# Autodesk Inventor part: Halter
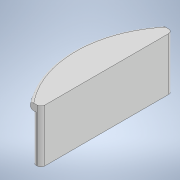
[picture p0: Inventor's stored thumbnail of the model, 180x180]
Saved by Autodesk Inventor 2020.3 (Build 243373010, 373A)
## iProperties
Created: 2020-07
Part Number: Halter
Material: Generisch
Document SubType Name: Modeling
Designer: Ruben
Density: 1 g/cm^3
Appearance: Vorgabe
Author: Ruben
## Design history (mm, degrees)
sketch "Skizze1"
  geometry: L1 (0, 0)-(0, 50); L2 (0, 0)-(45.605, 0); L3 (0, 50)-(5, 50); L4 (0, -50)-(5, -50); L5 (0, 50)-(0, -50); A1 r 80 centre (-57.45, 0) between (5, -50) and (5, 50)
  constraints: 10 end point, 2 horizontal, 2 point on circle, 2 symmetric about line, 1 centre point, 1 collinear, 1 vertical
  dimensions: "d0" = 50 distance of L1.start L1.end; "d1" = 5 distance of L1.end L3.end; "d2" = 80 radius of A1
extrude "Bogen" new body sketch "Skizze1" distance "d3" = 40; taper "d4" = 0 deg
sketch "Skizze2"
  geometry: L1 (-5, -50)-(-8, -50); L2 (0, 0)-(-34.59, 0); L3 (-5, 50)-(-8, 50); A1 r 80 centre (57.45, 0) between (-5, 50) and (-5, -50) reference; A2 r 80 centre (54.45, 0) between (-8, 50) and (-8, -50)
  constraints: 6 end point, 2 horizontal, 2 point on circle, 1 centre point, 1 equal radius, 1 symmetric about line
  dimensions: "d5" = 3 distance of L1.start L1.end
extrude "Lippe" join sketch "Skizze2" distance "d6" = 5; taper "d7" = 0 deg
sketch "Skizze3"
  geometry: L1 (0, 0)-(-33.741, 0); L2 (-8.25, -19.5)-(-3.75, -19.5); L3 (-3.75, -19.5)-(-3.75, 19.5); L4 (-3.75, 19.5)-(-8.25, 19.5); L5 (-8.25, 19.5)-(-8.25, -19.5); L6 (-8.25, -19.5)-(-3.75, 19.5); L7 (-3.75, -19.5)-(-8.25, 19.5); 1 further point
  constraints: 14 end point, 2 horizontal, 2 midpoint, 2 parallel, 1 perpendicular, 1 point on line
  dimensions: "d8" = 4.5 distance of L4.end L3.end; "d9" = 39 distance of L3.end L2.end; "d10" = 6 distance of L1.start point (-6, 0)
extrude "Montage" cut sketch "Skizze3" distance "d11" = 10; taper "d12" = 0 deg
fillet "Rundung_Lippe" dims "d13" = 2
fillet "Rundung_Kanten" dims "d14" = 3
node "Volumenkörper1"
